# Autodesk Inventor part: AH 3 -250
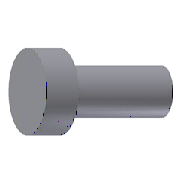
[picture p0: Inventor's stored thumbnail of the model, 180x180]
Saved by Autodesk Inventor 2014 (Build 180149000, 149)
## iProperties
IsCustomPart: 1
Created: 2009-11
Part Number: AH 3 -250
Material: DIN 1.2210
Description: Ejector pins-hardened
Document SubType Name: Modeling
Standard: DIN 1530/ISO 6751
Designer: gaom
Standard Revision: 1
Manufacturer: DME
Language: en-US
Size Designation: 3 -250
Categories: <MemberInstance><Categories><Category DisplayName="Mold" InternalName="349578f2-f4d4-4954-8c09-8e99297a61c0" Mnemonic="MOLD"><Category DisplayName="Ejector Comp
Mass: 0.191827 g
Surface Area: 2.51725 cm^2
Volume: 0.191827 cm^3
Density: 7.85 g/cm^3
Appearance: Anodized - Dark Gray
Author: gaom
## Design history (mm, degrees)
sketch "Sketch1"
  geometry: L1 (0, 3)-(3, 3); L2 (0, 0)-(0, 3); L3 (3, 1.5)-(250, 1.5); L4 (250, 1.5)-(250, 0); L5 (0, 0)-(250, 0); L6 (3, 3)-(3, 1.5); 2 further points
  constraints: 12 end point, 4 point on line, 2 horizontal, 2 perpendicular, 1 coincident
  dimensions: "d6" = 3 distance of L1.start L1.end (derived); "d9" = 250 distance between parallel lines of L4 L2 (derived); "d10" = 6 diameter of L1 L5 (derived); "d13" = 3 diameter of L3 L5 (derived)
revolve "Revolution1" sketch "Sketch1" stored, may be unused: angle "d11" = 90 deg
fillet "Fillet1" dims "d29" = 0.3 (derived)
workplane "Work Plane1"
sketch "Sketch2"
  geometry: L1 (3, -1.5)-(-3, -1.5) reference; L2 (-3, -1.5)-(-3, 1.5) reference; 4 further points
  constraints: 2 midpoint, 1 horizontal alignment, 1 vertical alignment
hole "Anti_Rotary Hole" sketch "Sketch2" at (0, 0) diameter "d44" = 0.55 (derived); stored, may be unused: countersink angle "d48" = 90 deg, drill point angle "d50" = 118 deg; dims "d45" = 6, "d46" = 4, "d47" = 2, "d49" = 0.825 (derived)
sketch "Sketch3"
  geometry: L1 (-1.8, 2.4)-(-1.8, -2.4); A1 r 3 centre (0, 0) between (-1.8, 2.4) and (-1.8, -2.4) reference; 1 further point
  constraints: 2 end point, 2 point on circle, 1 vertical
  dimensions: "d55" = 1.8 distance from line of point (0, 0) L1 (derived)
extrude "Anti_Rotary Plane" cut sketch "Sketch3" distance "d42" = 3.3 (derived); taper "d43" = 0 deg
feature "Sculpt1"
body "Solid1"
node "Projected Loop1"
feature "Surface1"
body "Srf1"
other parameters: "d15" = 0, "d24" = 0, "P" = 3 [user parameter], "T_" = 3 [user parameter], "H_" = 6 [user parameter], "R" = 0.3 [user parameter], "Anti_Rotary_P" = 1.8 [user parameter], "Anti_Rotary_D" = 0.55 [user parameter], "d51" = 0, "d54" = 0, "d56" = 0, "d57" = 0
